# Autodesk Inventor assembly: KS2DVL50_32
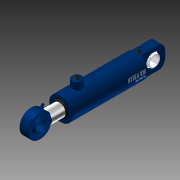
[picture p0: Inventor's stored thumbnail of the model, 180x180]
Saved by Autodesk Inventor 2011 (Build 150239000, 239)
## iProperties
Created: 2010-11
Document SubType Name: Assembly
Designer: TB
Mass: 566.294 g
Surface Area: 1153.75 cm^2
Volume: 566.294 cm^3
Density: 1 g/cm^3
Description: KS2DVL 50/32 - 100 mm
Slaglengde: 100,000 mm
Author: TB
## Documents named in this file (6)
- C:\Vault\Sylinderteknikk\Projects_ST\3D.nettkatalog\KS2-Series\KS2DVL\KS2DVL50_32\KS2DVL50_32.iam
- C:\Vault\Sylinderteknikk\Projects_ST\3D.nettkatalog\KS2-Series\KS2DVL\KS2DVL50_32\KS2DVL50_32_stang.ipt
- C:\Vault\Sylinderteknikk\Projects_ST\3D.nettkatalog\KS2-Series\KS2DVL\KS2DVL50_32\KS2DVL50_32_Parameters.ipt
- C:\Vault\Sylinderteknikk\Projects_ST\3D.nettkatalog\KS2-Series\KS2DVL\KS2DVL50_32\KS2DVL50_32_body..ipt
- C:\Vault\Sylinderteknikk\Projects_ST\Øyer\Klinkby.KS.Øyer\KS.25.øye.komplett\KS.eye25.ipt
- C:\Vault\Sylinderteknikk\Projects_ST\Øyer\Klinkby.KS.Øyer\KS.25.øye.komplett\KS.25.kule.ipt
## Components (5 placed, 5 different names)
1. KS2DVL50_32_Parameters:3
2. KS2DVL50_32_stang:1 — Mate:1, FriMate:2, Mate:3, Insert:2
3. KS2DVL50_32_body.:1 — Mate:1, FriMate:2, Mate:3, Insert:1, Angle:1
4. KS.eye25:1 — Insert:2, Angle:1
5. KS.25.kule:1 — Insert:1
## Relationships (6: Mate 3, Insert 2, Angle 1)
- Mate:1: KS2DVL50_32_stang:1 ↔ KS2DVL50_32_body.:1
- FriMate:2 [Mate]: KS2DVL50_32_stang:1 ↔ KS2DVL50_32_body.:1
- Mate:3: KS2DVL50_32_stang:1 ↔ KS2DVL50_32_body.:1
- Insert:1: KS2DVL50_32_body.:1 ↔ KS.25.kule:1
- Insert:2: KS2DVL50_32_stang:1 ↔ KS.eye25:1
- Angle:1: KS2DVL50_32_body.:1 ↔ KS.eye25:1
## Named parameters: Forlengelse_rør = 0, Vinkel_Minusport = 0
